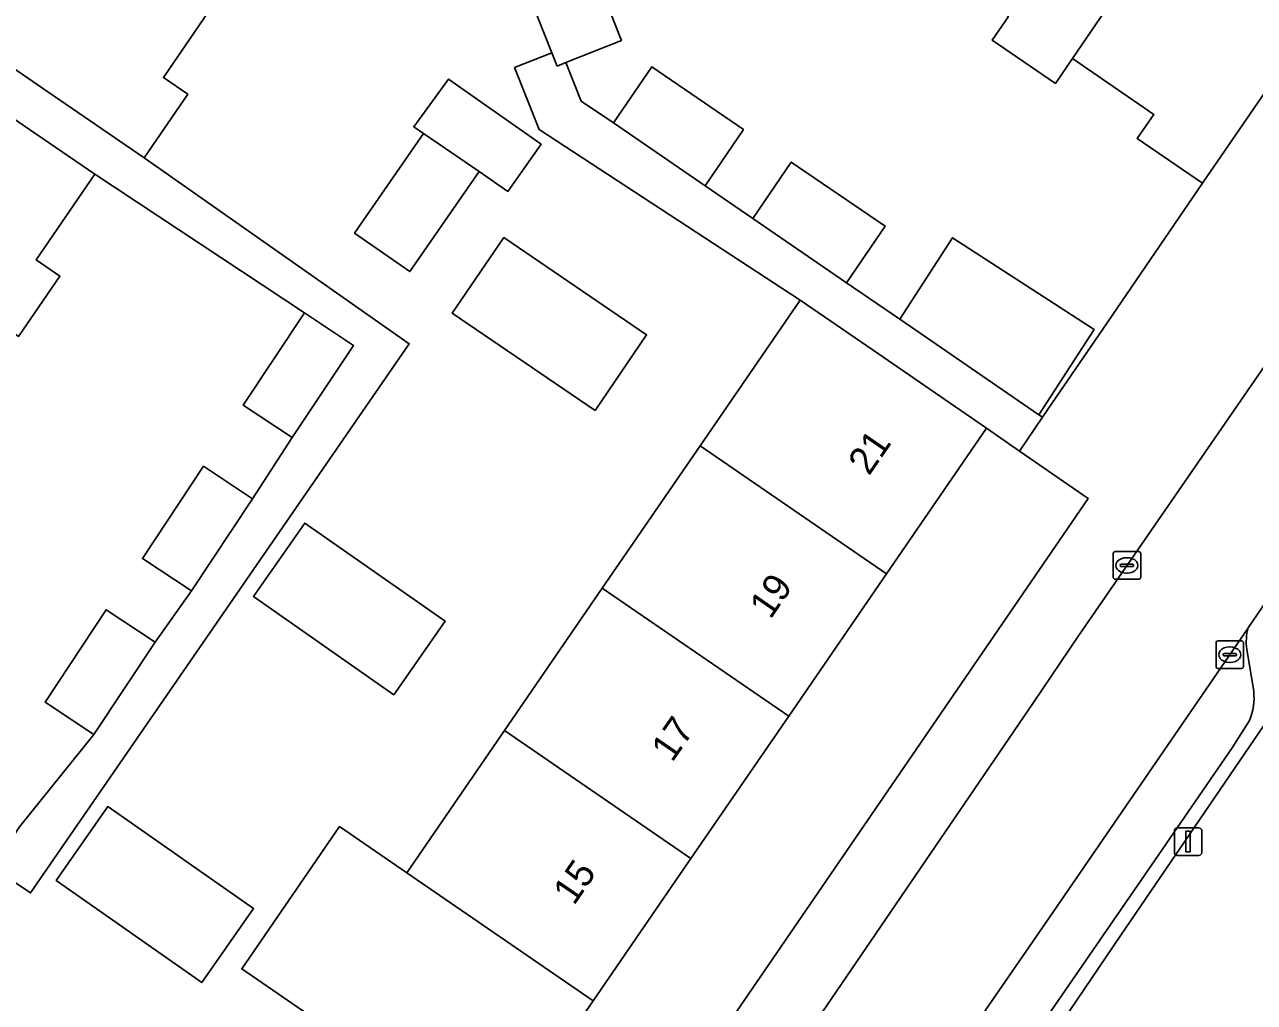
# Model space of a CAD drawing. Extents: x 160023 to 161302, y 384750 to 385707.
# Drawn here: x 160236.91 to 160281.58, y 385265.74 to 385301.25 of the extents above; entities that cross this region are included whole.
import ezdxf

# ---------------------------------------------------------------- set-up
doc = ezdxf.new("R2010")
doc.units = 0
for name, color, linetype in [('IMGEO_Erf', 7, 'Continuous'), ('IMGEO_Groenvoorziening', 7, 'Continuous'), ('IMGEO_Kolk', 7, 'Continuous'), ('IMGEO_Lichtmast', 7, 'Continuous'), ('IMGEO_Muur', 7, 'Continuous'), ('IMGEO_Pand', 7, 'Continuous'), ('IMGEO_Pand_nummerreeks', 7, 'Continuous'), ('IMGEO_Parkeervlak_open', 7, 'Continuous'), ('IMGEO_Rijbaan_lokaal_open', 7, 'Continuous'), ('IMGEO_Voetpad_open', 7, 'Continuous')]:
    doc.layers.add(name, color=color, linetype=linetype)

msp = doc.modelspace()

# ---------------------------------------------------------------- linework, layer by layer
at = {"layer": 'IMGEO_Erf'}
for points in [[(160257.379, 385303.73), (160258.593, 385300.673), (160256.577, 385299.872), (160257.134, 385298.471), (160258.299, 385297.679), (160259.696, 385299.717), (160263.025, 385297.435), (160261.629, 385295.398), (160263.359, 385294.212), (160264.763, 385296.259), (160268.168, 385293.925), (160266.763, 385291.878), (160268.701, 385290.55), (160270.621, 385293.511), (160275.761, 385290.179), (160273.755, 385287.085), (160273.889, 385286.993), (160274.095, 385287.295), (160276.078, 385290.196), (160279.695, 385295.488), (160277.327, 385297.112), (160277.928, 385297.989), (160274.973, 385300.016), (160274.357, 385299.112), (160272.057, 385300.69), (160272.646, 385301.548)], [(160248.349, 385272.128), (160250.797, 385270.447), (160254.346, 385275.616), (160257.896, 385280.785), (160261.446, 385285.955), (160265.081, 385291.248), (160255.598, 385297.438), (160254.713, 385299.692), (160256.066, 385300.229), (160255.043, 385302.802)], [(160243.583, 385301.699), (160241.956, 385299.327), (160242.838, 385298.722), (160241.254, 385296.411), (160250.884, 385289.663), (160237.133, 385269.719), (160235.748, 385270.636)], [(160236.732, 385272.121), (160239.433, 385275.471), (160237.656, 385276.648), (160239.876, 385279.998), (160241.652, 385278.821), (160242.971, 385280.684), (160241.195, 385281.861), (160243.414, 385285.211), (160245.191, 385284.034), (160246.635, 385286.253), (160244.858, 385287.431), (160247.078, 385290.78), (160239.462, 385295.817), (160237.33, 385292.713), (160238.195, 385292.119), (160236.689, 385289.928)], [(160227.053, 385213.278), (160252.215, 385250), (160275.542, 385284.043), (160273.047, 385285.762), (160271.852, 385286.599), (160268.217, 385281.306), (160264.667, 385276.136), (160261.117, 385270.967), (160257.567, 385265.798), (160254.017, 385260.628), (160250.467, 385255.458), (160246.918, 385250.289), (160246.719, 385250), (160243.368, 385245.119), (160239.734, 385239.828), (160234.941, 385243.119)], [(160233.569, 385251.847), (160237.12, 385257.017), (160240.147, 385254.938), (160243.697, 385260.107), (160247.247, 385265.277), (160244.799, 385266.958), (160248.349, 385272.128)]]:
    msp.add_lwpolyline(points, dxfattribs=at)
for points in [[(160248.899, 385293.672), (160251.404, 385297.294), (160251.047, 385297.539), (160252.309, 385299.27), (160255.675, 385296.908), (160254.471, 385295.191), (160253.421, 385295.91), (160250.911, 385292.28)], [(160254.321, 385293.523), (160259.508, 385289.987), (160257.634, 385287.239), (160252.448, 385290.774)], [(160245.226, 385280.483), (160247.092, 385283.15), (160252.19, 385279.581), (160250.323, 385276.915)], [(160239.939, 385272.85), (160245.228, 385269.147), (160243.352, 385266.466), (160238.062, 385270.169)]]:
    msp.add_lwpolyline(points, close=True, dxfattribs=at)
at = {"layer": 'IMGEO_Groenvoorziening'}
msp.add_lwpolyline([(160289.023, 385273.689), (160283.54, 385277.81), (160283.378, 385277.932), (160276.737, 385268.187), (160273.814, 385263.87), (160279.114, 385260.255)], close=True, dxfattribs=at)
at = {"layer": 'IMGEO_Kolk'}
for p, q in [((160276.452, 385281.185), (160276.452, 385282.037)), ((160276.527, 385282.111), (160277.379, 385282.111)), ((160276.94, 385281.891), (160276.965, 385281.891)), ((160277.453, 385282.037), (160277.453, 385281.185)), ((160276.711, 385281.605), (160276.711, 385281.617)), ((160277.149, 385281.568), (160276.751, 385281.568)), ((160276.754, 385281.654), (160277.152, 385281.654)), ((160277.195, 385281.617), (160277.195, 385281.605)), ((160277.379, 385281.111), (160276.527, 385281.111)), ((160276.963, 385281.331), (160276.938, 385281.331)), ((160280.19, 385277.944), (160280.19, 385278.796)), ((160280.265, 385278.87), (160281.117, 385278.87)), ((160281.191, 385278.796), (160281.191, 385277.944)), ((160280.449, 385278.364), (160280.449, 385278.376)), ((160280.887, 385278.327), (160280.489, 385278.327)), ((160280.492, 385278.413), (160280.89, 385278.413)), ((160280.678, 385278.65), (160280.703, 385278.65)), ((160280.933, 385278.376), (160280.933, 385278.364)), ((160281.117, 385277.87), (160280.265, 385277.87)), ((160280.701, 385278.09), (160280.676, 385278.09))]:
    msp.add_line(p, q, dxfattribs=at)
for points in [[(160276.452, 385281.185), (160276.452, 385282.037)], [(160276.527, 385282.111), (160277.379, 385282.111)], [(160277.453, 385282.037), (160277.453, 385281.185)], [(160277.379, 385281.111), (160276.527, 385281.111)], [(160280.19, 385277.944), (160280.19, 385278.796)], [(160280.265, 385278.87), (160281.117, 385278.87)], [(160281.191, 385278.796), (160281.191, 385277.944)], [(160281.117, 385277.87), (160280.265, 385277.87)]]:
    msp.add_lwpolyline(points, dxfattribs=at)
for centre, radius, start, end in [((160276.529, 385282.035), 0.0765, 91.552, 178.448), ((160276.529, 385282.035), 0.0765, 91.552, 178.448), ((160277.377, 385282.035), 0.0765, 1.552, 88.448), ((160277.377, 385282.035), 0.0765, 1.552, 88.448), ((160276.751, 385281.614), 0.0403, 85.8775, 175.7526), ((160276.748, 385281.604), 0.0366, 178.938, 274.7102), ((160277.152, 385281.611), 0.043, 264.8664, 352.4533), ((160277.156, 385281.616), 0.0386, 1.7309, 96.639), ((160276.529, 385281.187), 0.0765, 181.552, 268.448), ((160276.529, 385281.187), 0.0765, 181.552, 268.448), ((160277.377, 385281.187), 0.0765, 271.552, 358.448), ((160277.377, 385281.187), 0.0765, 271.552, 358.448), ((160280.267, 385278.794), 0.0765, 91.552, 178.448), ((160280.267, 385278.794), 0.0765, 91.552, 178.448), ((160281.115, 385278.794), 0.0765, 1.552, 88.448), ((160281.115, 385278.794), 0.0765, 1.552, 88.448), ((160280.489, 385278.373), 0.0403, 85.8775, 175.7526), ((160280.486, 385278.363), 0.0366, 178.938, 274.7102), ((160280.89, 385278.37), 0.043, 264.8664, 352.4533), ((160280.894, 385278.375), 0.0386, 1.7309, 96.639), ((160280.267, 385277.946), 0.0765, 181.552, 268.448), ((160280.267, 385277.946), 0.0765, 181.552, 268.448), ((160281.115, 385277.946), 0.0765, 271.552, 358.448), ((160281.115, 385277.946), 0.0765, 271.552, 358.448)]:
    msp.add_arc(centre, radius, start, end, dxfattribs=at)
for centre, major_axis, ratio, start_param, end_param in [((160276.939, 385281.611), (-0.387, 0.002), 0.722429, 4.712389, 7.853982), ((160276.964, 385281.611), (-0.39, 0.002), 0.717154, 1.570796, 4.712389), ((160280.677, 385278.37), (-0.387, 0.002), 0.722429, 4.712389, 7.853982), ((160280.702, 385278.37), (-0.39, 0.002), 0.717154, 1.570796, 4.712389)]:
    msp.add_ellipse(centre, major_axis=major_axis, ratio=ratio, start_param=start_param, end_param=end_param, dxfattribs=at)
at = {"layer": 'IMGEO_Lichtmast'}
for p, q in [((160278.779, 385272.08), (160279.569, 385272.08)), ((160279.569, 385272.08), (160278.779, 385272.08)), ((160278.679, 385271.18), (160278.679, 385271.98)), ((160278.679, 385271.98), (160278.679, 385271.18)), ((160279.669, 385271.98), (160279.669, 385271.18)), ((160279.669, 385271.18), (160279.669, 385271.98)), ((160279.569, 385271.08), (160278.779, 385271.08)), ((160278.779, 385271.08), (160279.569, 385271.08))]:
    msp.add_line(p, q, dxfattribs=at)
msp.add_lwpolyline([(160279.099, 385271.955), (160279.249, 385271.955), (160279.249, 385271.205), (160279.099, 385271.205), (160279.099, 385271.955)], dxfattribs=at)
for centre, start, end in [((160278.779, 385271.98), 90, 180), ((160278.779, 385271.98), 90, 180), ((160279.569, 385271.98), 0, 90), ((160279.569, 385271.98), 360, 90), ((160278.779, 385271.18), 180, 270), ((160278.779, 385271.18), 180, 270), ((160279.569, 385271.18), 270, 0), ((160279.569, 385271.18), 270, 0)]:
    msp.add_arc(centre, 0.1, start, end, dxfattribs=at)
at = {"layer": 'IMGEO_Muur'}
msp.add_lwpolyline([(160276.078, 385290.196), (160279.695, 385295.488)], dxfattribs=at)
at = {"layer": 'IMGEO_Pand'}
for points in [[(160279.455, 385306.587), (160274.212, 385310.163), (160269.139, 385302.726), (160269.237, 385302.659), (160269.809, 385303.494), (160272.646, 385301.548), (160272.057, 385300.69), (160274.357, 385299.112), (160274.973, 385300.016)], [(160244.031, 385302.352), (160237.292, 385306.975), (160233.632, 385301.638), (160237.756, 385298.81), (160241.254, 385296.411), (160242.838, 385298.722), (160241.956, 385299.327), (160243.583, 385301.699)], [(160284.805, 385302.938), (160279.455, 385306.587), (160274.973, 385300.016), (160277.928, 385297.989), (160277.327, 385297.112), (160279.695, 385295.488)], [(160257.379, 385303.73), (160255.043, 385302.802), (160256.066, 385300.229), (160256.258, 385299.745), (160256.577, 385299.872), (160258.593, 385300.673)], [(160239.462, 385295.817), (160236.865, 385297.603), (160232.744, 385300.433), (160229.106, 385295.139), (160235.848, 385290.506), (160236.689, 385289.928), (160238.195, 385292.119), (160237.33, 385292.713)], [(160258.299, 385297.679), (160261.629, 385295.398), (160263.025, 385297.435), (160259.696, 385299.717)], [(160251.404, 385297.294), (160253.421, 385295.91), (160254.471, 385295.191), (160255.675, 385296.908), (160252.309, 385299.27), (160251.047, 385297.539)], [(160253.421, 385295.91), (160251.404, 385297.294), (160248.899, 385293.672), (160250.911, 385292.28)], [(160263.359, 385294.212), (160266.763, 385291.878), (160268.168, 385293.925), (160264.763, 385296.259)], [(160259.508, 385289.987), (160254.321, 385293.523), (160252.448, 385290.774), (160257.634, 385287.239)], [(160268.701, 385290.55), (160273.755, 385287.085), (160275.761, 385290.179), (160270.621, 385293.511)], [(160268.217, 385281.306), (160271.852, 385286.599), (160267.731, 385289.429), (160265.081, 385291.248), (160261.446, 385285.955)], [(160247.078, 385290.78), (160244.858, 385287.431), (160246.635, 385286.253), (160248.855, 385289.603)], [(160261.446, 385285.955), (160257.896, 385280.785), (160264.667, 385276.136), (160268.217, 385281.306)], [(160243.414, 385285.211), (160241.195, 385281.861), (160242.971, 385280.684), (160245.191, 385284.034)], [(160252.19, 385279.581), (160247.092, 385283.15), (160245.226, 385280.483), (160250.323, 385276.915)], [(160261.117, 385270.967), (160264.667, 385276.136), (160257.896, 385280.785), (160254.346, 385275.616)], [(160239.876, 385279.998), (160237.656, 385276.648), (160239.433, 385275.471), (160241.652, 385278.821)], [(160254.346, 385275.616), (160250.797, 385270.447), (160257.567, 385265.798), (160261.117, 385270.967)], [(160245.228, 385269.147), (160239.939, 385272.85), (160238.062, 385270.169), (160243.352, 385266.466)], [(160257.567, 385265.798), (160250.797, 385270.447), (160248.349, 385272.128), (160244.799, 385266.958), (160247.247, 385265.277), (160254.017, 385260.628)]]:
    msp.add_lwpolyline(points, close=True, dxfattribs=at)
at = {"layer": 'IMGEO_Parkeervlak_open'}
for points in [[(160281.354, 385279.339), (160281.342, 385279.321), (160274.133, 385268.809), (160237.121, 385215.152)], [(160281.56, 385277.031), (160281.303, 385278.571)], [(160240.882, 385216.735), (160251.376, 385232.207), (160258.548, 385242.626), (160261.715, 385247.262), (160270.57, 385260.175), (160273.341, 385264.193), (160277.715, 385270.535), (160280.777, 385274.991), (160281.411, 385275.98)]]:
    msp.add_lwpolyline(points, dxfattribs=at)
for centre, radius, start, end in [((160283.381, 385278.819), 2.093, 165.6047, 186.7968), ((160279.275, 385276.819), 2.295, 338.5577, 5.3042)]:
    msp.add_arc(centre, radius, start, end, dxfattribs=at)
at = {"layer": 'IMGEO_Rijbaan_lokaal_open'}
for points in [[(160289.671, 385300.047), (160275.192, 385279.056), (160273.555, 385276.635), (160266.052, 385265.629), (160255.317, 385250), (160244.457, 385234.203), (160242.319, 385231.091), (160233.518, 385218.28), (160231.382, 385215.171), (160229.193, 385211.984)], [(160274.133, 385268.809), (160281.342, 385279.321), (160281.354, 385279.339), (160281.858, 385280.074), (160293.52, 385297.079)], [(160232.364, 385208.255), (160237.121, 385215.152), (160274.133, 385268.809)]]:
    msp.add_lwpolyline(points, dxfattribs=at)
at = {"layer": 'IMGEO_Voetpad_open'}
for points in [[(160266.052, 385265.629), (160273.555, 385276.635), (160275.192, 385279.056), (160289.671, 385300.047), (160285.654, 385304.118), (160284.805, 385302.938), (160279.695, 385295.488), (160276.078, 385290.196), (160274.095, 385287.295), (160273.889, 385286.993), (160273.047, 385285.762), (160275.542, 385284.043), (160252.215, 385250), (160227.053, 385213.278)], [(160296.398, 385295.385), (160293.52, 385297.079), (160281.858, 385280.074), (160281.354, 385279.339)], [(160234.684, 385206.643), (160244.303, 385220.626), (160245.244, 385222.066), (160259.132, 385242.227), (160260.026, 385243.56), (160264.456, 385250), (160273.04, 385262.479), (160273.814, 385263.87), (160276.737, 385268.187), (160283.378, 385277.932), (160284.321, 385279.384), (160291.84, 385290.346)], [(160281.303, 385278.571), (160281.56, 385277.031)], [(160281.411, 385275.98), (160280.777, 385274.991), (160277.715, 385270.535), (160273.341, 385264.193), (160270.57, 385260.175), (160261.715, 385247.262), (160258.548, 385242.626), (160251.376, 385232.207), (160240.882, 385216.735)]]:
    msp.add_lwpolyline(points, dxfattribs=at)
for points in [[(160250.884, 385289.663), (160241.254, 385296.411), (160237.756, 385298.81), (160233.632, 385301.638), (160233.168, 385301.956), (160232.322, 385300.723), (160232.744, 385300.433), (160236.865, 385297.603), (160239.462, 385295.817), (160247.078, 385290.78), (160248.855, 385289.603), (160246.635, 385286.253), (160245.191, 385284.034), (160242.971, 385280.684), (160241.652, 385278.821), (160239.433, 385275.471), (160236.732, 385272.121), (160235.748, 385270.636), (160237.133, 385269.719)], [(160263.359, 385294.212), (160261.629, 385295.398), (160258.299, 385297.679), (160257.134, 385298.471), (160256.577, 385299.872), (160256.258, 385299.745), (160256.066, 385300.229), (160254.713, 385299.692), (160255.598, 385297.438), (160265.081, 385291.248), (160267.731, 385289.429), (160271.852, 385286.599), (160273.047, 385285.762), (160273.889, 385286.993), (160273.755, 385287.085), (160268.701, 385290.55), (160266.763, 385291.878)]]:
    msp.add_lwpolyline(points, close=True, dxfattribs=at)
for centre, radius, start, end in [((160283.381, 385278.819), 2.093, 165.6047, 186.7968), ((160279.275, 385276.819), 2.295, 338.5577, 5.3042)]:
    msp.add_arc(centre, radius, start, end, dxfattribs=at)

# ---------------------------------------------------------------- texts
at = {"layer": 'IMGEO_Pand_nummerreeks'}
for s, p in [('21', (160267.586, 385284.839)), ('19', (160264.005, 385279.624)), ('17', (160260.437, 385274.428)), ('15', (160256.868, 385269.231))]:
    msp.add_text(s, height=1, rotation=55.5223, dxfattribs=at).set_placement(p)

doc.saveas('drawing.dxf')
